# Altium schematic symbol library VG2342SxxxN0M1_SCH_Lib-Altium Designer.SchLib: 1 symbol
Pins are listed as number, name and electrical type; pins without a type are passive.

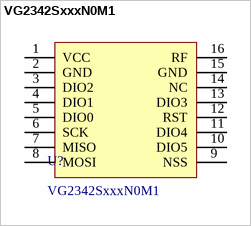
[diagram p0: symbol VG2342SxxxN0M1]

## VG2342SxxxN0M1
designator U?
pins: 1 VCC, 2 GND, 3 DIO2, 4 DIO1, 5 DIO0, 6 SCK, 7 MISO, 8 MOSI, 9 NSS, 10 DIO5, 11 DIO4, 12 RST, 13 DIO3, 14 NC, 15 GND, 16 RF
